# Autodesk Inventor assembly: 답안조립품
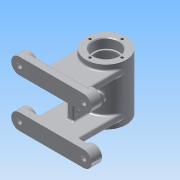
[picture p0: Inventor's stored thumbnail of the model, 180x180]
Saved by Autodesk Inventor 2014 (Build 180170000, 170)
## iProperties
Created: 2015-11
Part Number: 답안조립품
Document SubType Name: Assembly
Designer: 106-16
Author: 106-16
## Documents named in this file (2)
- C:\Users\106-16\Desktop\451110V1015\답안조립품.iam
- C:\Users\106-16\Desktop\451110V1015\1-본체.ipt
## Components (1 placed, 1 different names)
1. 1-본체:1
